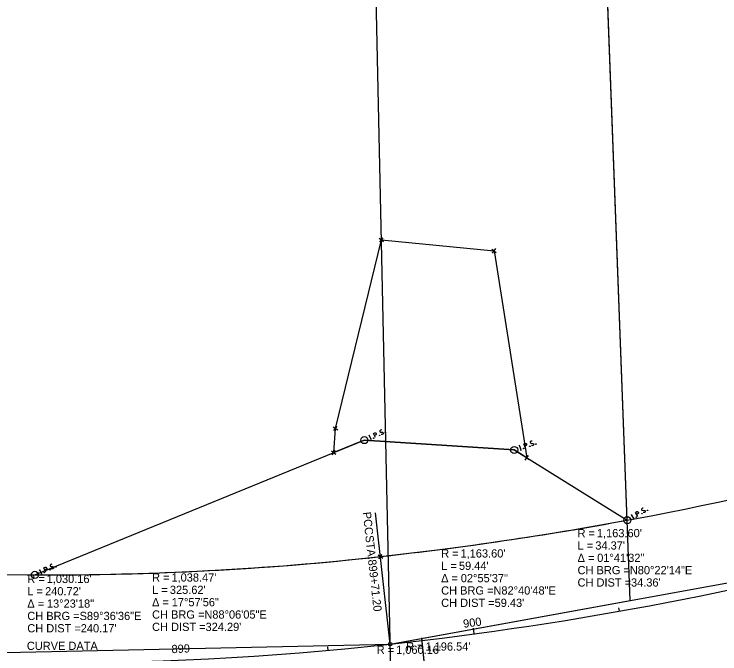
# Model space of a CAD drawing. Extents: x 2379325 to 2382869, y 256594 to 258871.
# Drawn here: x 2382072.5 to 2382312.6, y 257889.6 to 258107.4 of the extents above; entities that cross this region are included whole.
import ezdxf

# ---------------------------------------------------------------- set-up
doc = ezdxf.new("R2010")
doc.units = 0
for name, color, linetype in [('Default', 7, 'Continuous'), ('DR_P_Culvert3D', 7, 'Continuous'), ('DR_P_Dike', 7, 'Continuous'), ('DR_P_Ditch', 7, 'Continuous'), ('DR_P_Drainage_Area', 7, 'Continuous'), ('DR_P_GenericNode', 7, 'Continuous'), ('DR_P_Headwall', 7, 'Continuous'), ('DR_P_Storm_Sewer', 7, 'Continuous'), ('DR_X_Culvert', 7, 'Continuous'), ('DR_X_Culvert3D', 7, 'Continuous'), ('DR_X_Storm_Sewer', 7, 'Continuous'), ('PF_X_Ground_Line', 7, 'Continuous'), ('PTS_PVMT', 7, 'Continuous'), ('SC_Scratch2', 7, 'Continuous'), ('SC_Scratch3', 7, 'Continuous'), ('SC_Scratch4', 7, 'Continuous')]:
    doc.layers.add(name, color=color, linetype=linetype)

msp = doc.modelspace()

# ---------------------------------------------------------------- linework, layer by layer
at = {"layer": 'DR_P_Culvert3D'}
msp.add_lwpolyline([(2382181.25, 257958.12), (2382181.87, 257966.38), (2382197.46, 258030.5), (2382235.79, 258026.77), (2382246.91, 257956.37)], dxfattribs=at)
at = {"layer": 'DR_P_Dike'}
for p, q in [((2382079.62, 257916.52), (2382191.66, 257962.38)), ((2382191.66, 257962.38), (2382242.64, 257959.02)), ((2382191.66, 257962.38), (2382242.64, 257959.02)), ((2382242.64, 257959.02), (2382281.1, 257935.12))]:
    msp.add_line(p, q, dxfattribs=at)
for centre, radius, start, end in [((2382069.07, 259082.23), 1166.54, 276.30412, 280.47247), ((2382084.05, 258946.67), 1030.16, 269.75391, 276.30412)]:
    msp.add_arc(centre, radius, start, end, dxfattribs=at)
at = {"layer": 'DR_P_Ditch'}
for points in [[(2382193.16, 257963.95), (2382193.48, 257964.09)], [(2382193.99, 257962.56), (2382193.32, 257964.02)], [(2382195.41, 257963.21), (2382194.75, 257964.67), (2382195.23, 257964.89), (2382195.28, 257964.9), (2382195.36, 257964.91), (2382195.4, 257964.9), (2382195.44, 257964.89), (2382195.51, 257964.85), (2382195.57, 257964.81), (2382195.63, 257964.72), (2382195.69, 257964.59), (2382195.7, 257964.54), (2382195.71, 257964.46), (2382195.71, 257964.36), (2382195.69, 257964.31), (2382195.67, 257964.27), (2382195.63, 257964.22), (2382195.55, 257964.18), (2382195.07, 257963.96)], [(2382196.82, 257964.09), (2382196.87, 257964.11), (2382196.91, 257964.1), (2382196.96, 257964.07), (2382196.98, 257964.01), (2382196.97, 257963.95), (2382196.95, 257963.92), (2382196.9, 257963.89), (2382196.86, 257963.9), (2382196.81, 257963.94), (2382196.79, 257963.99), (2382196.8, 257964.05), (2382196.82, 257964.09)], [(2382197.53, 257965.81), (2382197.5, 257965.83), (2382197.46, 257965.84), (2382197.35, 257965.83), (2382197.23, 257965.8), (2382197.15, 257965.77), (2382197.12, 257965.75), (2382197.01, 257965.66), (2382196.93, 257965.54), (2382196.9, 257965.42), (2382196.92, 257965.31), (2382196.95, 257965.25), (2382197.02, 257965.16), (2382197.13, 257965.12), (2382197.84, 257965.03), (2382197.91, 257965), (2382197.95, 257964.97), (2382198, 257964.91), (2382198.04, 257964.84), (2382198.06, 257964.77), (2382198.07, 257964.72), (2382198.07, 257964.65), (2382198.08, 257964.59), (2382198.07, 257964.55), (2382198.06, 257964.5), (2382198.04, 257964.47), (2382198.01, 257964.42), (2382197.98, 257964.4), (2382197.9, 257964.35), (2382197.76, 257964.28), (2382197.66, 257964.26), (2382197.49, 257964.29), (2382197.38, 257964.32)], [(2382198.8, 257964.99), (2382198.85, 257965.02), (2382198.89, 257965.01), (2382198.94, 257964.98), (2382198.97, 257964.92), (2382198.96, 257964.86), (2382198.94, 257964.82), (2382198.89, 257964.8), (2382198.85, 257964.81), (2382198.8, 257964.84), (2382198.77, 257964.9), (2382198.78, 257964.96), (2382198.8, 257964.99)], [(2382193.83, 257962.49), (2382194.15, 257962.64)], [(2382194.77, 257963.16), (2382194.82, 257963.18), (2382194.86, 257963.17), (2382194.91, 257963.14), (2382194.94, 257963.08), (2382194.93, 257963.02), (2382194.91, 257962.98), (2382194.86, 257962.96), (2382194.82, 257962.97), (2382194.77, 257963), (2382194.74, 257963.06), (2382194.75, 257963.12), (2382194.77, 257963.16)], [(2382248.74, 257962.03), (2382248.71, 257962.05), (2382248.67, 257962.06), (2382248.57, 257962.06), (2382248.45, 257962.04), (2382248.36, 257962.01), (2382248.33, 257962), (2382248.21, 257961.92), (2382248.12, 257961.8), (2382248.09, 257961.68), (2382248.1, 257961.58), (2382248.13, 257961.51), (2382248.18, 257961.42), (2382248.3, 257961.37), (2382249, 257961.23), (2382249.07, 257961.2), (2382249.1, 257961.16), (2382249.15, 257961.1), (2382249.18, 257961.03), (2382249.19, 257960.95), (2382249.2, 257960.9), (2382249.2, 257960.83), (2382249.2, 257960.78), (2382249.19, 257960.74), (2382249.18, 257960.69), (2382249.15, 257960.65), (2382249.12, 257960.61), (2382249.09, 257960.59), (2382249.01, 257960.54), (2382248.86, 257960.49), (2382248.76, 257960.48), (2382248.59, 257960.51), (2382248.48, 257960.55)], [(2382244.25, 257960.48), (2382244.58, 257960.6)], [(2382244.98, 257959.04), (2382244.42, 257960.54)], [(2382244.81, 257958.98), (2382245.14, 257959.1)], [(2382245.8, 257959.58), (2382245.85, 257959.6), (2382245.89, 257959.58), (2382245.94, 257959.55), (2382245.96, 257959.49), (2382245.95, 257959.43), (2382245.93, 257959.4), (2382245.88, 257959.38), (2382245.84, 257959.39), (2382245.79, 257959.42), (2382245.77, 257959.48), (2382245.78, 257959.54), (2382245.8, 257959.58)], [(2382246.44, 257959.59), (2382245.88, 257961.09), (2382246.38, 257961.27), (2382246.44, 257961.28), (2382246.52, 257961.28), (2382246.56, 257961.27), (2382246.6, 257961.26), (2382246.66, 257961.22), (2382246.71, 257961.17), (2382246.77, 257961.08), (2382246.82, 257960.94), (2382246.83, 257960.89), (2382246.84, 257960.81), (2382246.82, 257960.71), (2382246.8, 257960.66), (2382246.77, 257960.63), (2382246.73, 257960.58), (2382246.65, 257960.54), (2382246.16, 257960.36)], [(2382247.91, 257960.36), (2382247.96, 257960.38), (2382248, 257960.37), (2382248.05, 257960.34), (2382248.07, 257960.28), (2382248.06, 257960.22), (2382248.03, 257960.18), (2382247.98, 257960.16), (2382247.94, 257960.17), (2382247.89, 257960.21), (2382247.87, 257960.27), (2382247.89, 257960.33), (2382247.91, 257960.36)], [(2382249.95, 257961.13), (2382250, 257961.15), (2382250.04, 257961.13), (2382250.09, 257961.1), (2382250.11, 257961.04), (2382250.1, 257960.98), (2382250.08, 257960.95), (2382250.03, 257960.93), (2382249.99, 257960.94), (2382249.94, 257960.97), (2382249.92, 257961.03), (2382249.93, 257961.09), (2382249.95, 257961.13)], [(2382284.74, 257936.38), (2382283.91, 257937.75), (2382284.36, 257938.03), (2382284.41, 257938.04), (2382284.49, 257938.06), (2382284.53, 257938.06), (2382284.57, 257938.05), (2382284.64, 257938.02), (2382284.71, 257937.99), (2382284.78, 257937.91), (2382284.86, 257937.78), (2382284.87, 257937.73), (2382284.89, 257937.66), (2382284.9, 257937.56), (2382284.88, 257937.5), (2382284.87, 257937.47), (2382284.83, 257937.42), (2382284.76, 257937.36), (2382284.31, 257937.09)], [(2382286.54, 257939.21), (2382286.51, 257939.22), (2382286.47, 257939.23), (2382286.36, 257939.21), (2382286.25, 257939.17), (2382286.17, 257939.12), (2382286.14, 257939.11), (2382286.04, 257939), (2382285.97, 257938.87), (2382285.96, 257938.75), (2382285.99, 257938.65), (2382286.03, 257938.58), (2382286.1, 257938.51), (2382286.22, 257938.48), (2382286.94, 257938.47), (2382287.01, 257938.46), (2382287.06, 257938.42), (2382287.12, 257938.37), (2382287.15, 257938.31), (2382287.18, 257938.24), (2382287.2, 257938.19), (2382287.21, 257938.12), (2382287.22, 257938.07), (2382287.22, 257938.02), (2382287.21, 257937.97), (2382287.2, 257937.93), (2382287.17, 257937.89), (2382287.15, 257937.86), (2382287.07, 257937.8), (2382286.94, 257937.72), (2382286.84, 257937.69), (2382286.68, 257937.69), (2382286.56, 257937.71)], [(2382286.03, 257937.42), (2382286.08, 257937.45), (2382286.12, 257937.44), (2382286.17, 257937.42), (2382286.2, 257937.36), (2382286.2, 257937.3), (2382286.19, 257937.26), (2382286.14, 257937.24), (2382286.1, 257937.24), (2382286.04, 257937.27), (2382286.01, 257937.32), (2382286.01, 257937.38), (2382286.03, 257937.42)], [(2382287.9, 257938.55), (2382287.94, 257938.58), (2382287.98, 257938.57), (2382288.04, 257938.55), (2382288.07, 257938.49), (2382288.07, 257938.43), (2382288.05, 257938.39), (2382288.01, 257938.37), (2382287.97, 257938.37), (2382287.91, 257938.4), (2382287.88, 257938.45), (2382287.88, 257938.51), (2382287.9, 257938.55)], [(2382282.42, 257936.85), (2382282.72, 257937.03)], [(2382283.4, 257935.57), (2382282.57, 257936.94)], [(2382283.25, 257935.48), (2382283.55, 257935.67)], [(2382284.11, 257936.25), (2382284.15, 257936.28), (2382284.19, 257936.28), (2382284.25, 257936.25), (2382284.28, 257936.2), (2382284.28, 257936.14), (2382284.26, 257936.1), (2382284.22, 257936.07), (2382284.18, 257936.07), (2382284.12, 257936.1), (2382284.09, 257936.15), (2382284.09, 257936.22), (2382284.11, 257936.25)], [(2382081.09, 257918.12), (2382081.41, 257918.28)], [(2382081.95, 257916.76), (2382081.25, 257918.2)], [(2382083.35, 257917.44), (2382082.66, 257918.88), (2382083.13, 257919.11), (2382083.19, 257919.12), (2382083.27, 257919.13), (2382083.31, 257919.13), (2382083.35, 257919.12), (2382083.42, 257919.08), (2382083.48, 257919.04), (2382083.54, 257918.96), (2382083.61, 257918.82), (2382083.62, 257918.77), (2382083.63, 257918.69), (2382083.63, 257918.59), (2382083.61, 257918.54), (2382083.59, 257918.5), (2382083.55, 257918.46), (2382083.47, 257918.41), (2382083, 257918.18)], [(2382084.74, 257918.35), (2382084.79, 257918.37), (2382084.83, 257918.36), (2382084.88, 257918.33), (2382084.91, 257918.28), (2382084.9, 257918.22), (2382084.88, 257918.18), (2382084.83, 257918.16), (2382084.79, 257918.16), (2382084.74, 257918.19), (2382084.71, 257918.25), (2382084.72, 257918.31), (2382084.74, 257918.35)], [(2382085.42, 257920.09), (2382085.39, 257920.1), (2382085.35, 257920.11), (2382085.24, 257920.1), (2382085.12, 257920.07), (2382085.04, 257920.03), (2382085.01, 257920.02), (2382084.9, 257919.92), (2382084.82, 257919.8), (2382084.8, 257919.68), (2382084.82, 257919.58), (2382084.85, 257919.51), (2382084.92, 257919.43), (2382085.03, 257919.39), (2382085.74, 257919.31), (2382085.82, 257919.29), (2382085.86, 257919.25), (2382085.91, 257919.19), (2382085.94, 257919.13), (2382085.97, 257919.05), (2382085.98, 257919), (2382085.99, 257918.94), (2382085.99, 257918.88), (2382085.98, 257918.84), (2382085.97, 257918.79), (2382085.95, 257918.75), (2382085.92, 257918.71), (2382085.9, 257918.69), (2382085.82, 257918.63), (2382085.68, 257918.56), (2382085.58, 257918.54), (2382085.41, 257918.56), (2382085.3, 257918.59)], [(2382086.71, 257919.3), (2382086.75, 257919.32), (2382086.8, 257919.31), (2382086.85, 257919.28), (2382086.87, 257919.23), (2382086.87, 257919.17), (2382086.85, 257919.13), (2382086.8, 257919.11), (2382086.76, 257919.11), (2382086.71, 257919.14), (2382086.68, 257919.2), (2382086.69, 257919.26), (2382086.71, 257919.3)], [(2382081.79, 257916.68), (2382082.1, 257916.84)], [(2382082.72, 257917.37), (2382082.77, 257917.39), (2382082.81, 257917.39), (2382082.86, 257917.35), (2382082.89, 257917.3), (2382082.88, 257917.24), (2382082.86, 257917.2), (2382082.81, 257917.18), (2382082.77, 257917.18), (2382082.72, 257917.22), (2382082.69, 257917.27), (2382082.7, 257917.33), (2382082.72, 257917.37)]]:
    msp.add_lwpolyline(points, dxfattribs=at)
for centre in [(2382191.66, 257962.38), (2382242.64, 257959.02), (2382281.1, 257935.12), (2382079.62, 257916.52)]:
    msp.add_circle(centre, 1.2, dxfattribs=at)
at = {"layer": 'DR_P_Drainage_Area'}
for p, q in [((2382181.87, 257966.38), (2382197.46, 258030.5)), ((2382197.46, 258030.5), (2382235.79, 258026.77)), ((2382235.79, 258026.77), (2382246.91, 257956.37)), ((2382181.25, 257958.12), (2382181.87, 257966.38)), ((2382191.66, 257962.38), (2382181.25, 257958.12)), ((2382242.64, 257959.02), (2382191.66, 257962.38)), ((2382246.91, 257956.37), (2382242.64, 257959.02))]:
    msp.add_line(p, q, dxfattribs=at)
at = {"layer": 'DR_P_GenericNode'}
msp.add_arc((2382069.07, 259082.23), 1196.54, 276.30412, 294.50972, dxfattribs=at)
at = {"layer": 'DR_P_Headwall'}
for centre, radius, start, end in [((2382069.07, 259082.23), 1166.54, 276.30412, 294.58836), ((2382069.07, 259082.23), 1226.54, 276.30412, 294.43398), ((2382084.05, 258946.67), 1030.16, 262.91573, 276.30412)]:
    msp.add_arc(centre, radius, start, end, dxfattribs=at)
at = {"layer": 'DR_P_Storm_Sewer'}
for p, q in [((2382196.7, 258031.07), (2382198.21, 258029.92)), ((2382196.89, 258029.74), (2382198.02, 258031.25)), ((2382235.02, 258027.33), (2382236.55, 258026.22)), ((2382235.24, 258026.01), (2382236.34, 258027.54)), ((2382181.11, 257966.94), (2382182.63, 257965.83)), ((2382181.32, 257965.62), (2382182.43, 257967.14)), ((2382180.5, 257958.69), (2382181.99, 257957.54)), ((2382180.67, 257957.37), (2382181.82, 257958.86)), ((2382246.13, 257956.91), (2382247.68, 257955.83)), ((2382246.37, 257955.6), (2382247.45, 257957.14)), ((2382196.42, 257923.32), (2382197.91, 257922.16)), ((2382196.59, 257922), (2382197.74, 257923.49))]:
    msp.add_line(p, q, dxfattribs=at)
at = {"layer": 'DR_X_Culvert3D'}
for p, q in [((2382278.44, 257904.15), (2382278.23, 257905.33)), ((2382229.04, 257896.43), (2382228.78, 257898.41)), ((2382179.36, 257890.81), (2382179.26, 257892))]:
    msp.add_line(p, q, dxfattribs=at)
at = {"layer": 'DR_X_Storm_Sewer'}
for p, q in [((2382282.14, 257907.78), (2382270.85, 258207.56)), ((2382200.46, 257892.92), (2382358.38, 257921.64)), ((2382240.29, 257605.16), (2382211.21, 257895.08)), ((2382240.29, 257605.16), (2382211.23, 257894.88)), ((2382069.47, 257890.07), (2382200.46, 257892.92))]:
    msp.add_line(p, q, dxfattribs=at)
at = {"layer": 'PF_X_Ground_Line'}
msp.add_line((2382227.19, 256666.69), (2382192.17, 258272.85), dxfattribs=at)
at = {"layer": 'PTS_PVMT'}
msp.add_lwpolyline([(2380915.57, 257974.64), (2381892.11, 257902.21), (2381953.3, 257894.61), (2382069.47, 257890.07), (2382200.46, 257892.92), (2382282.14, 257907.78), (2382270.85, 258207.56), (2382395.58, 258240.12), (2382408.52, 258119.54), (2382529.94, 258163.94), (2382565.45, 257993.51), (2382716.17, 258049.69), (2382661.23, 258620.32), (2382184.82, 258609.93), (2381665.09, 258580.43), (2381008.69, 258600.49), (2380481.9, 258662.85), (2379503.04, 258870.93), (2379508.92, 258601.15), (2380163.69, 258211.64)], dxfattribs=at)
at = {"layer": 'SC_Scratch2'}
for centre, radius, start, end in [((2382069.07, 259082.23), 1196.54, 276.30412, 294.50972), ((2382084.05, 258946.67), 1060.16, 262.91573, 276.30412)]:
    msp.add_arc(centre, radius, start, end, dxfattribs=at)
at = {"layer": 'SC_Scratch3'}
msp.add_line((2382200.46, 257892.92), (2382195.52, 257937.65), dxfattribs=at)
msp.add_circle((2382200.46, 257892.92), 0.6, dxfattribs=at)
at = {"layer": 'SC_Scratch4'}
for p, q in [((2382079.62, 257916.52), (2382191.66, 257962.38)), ((2382191.66, 257962.38), (2382242.64, 257959.02)), ((2382242.64, 257959.02), (2382281.1, 257935.12))]:
    msp.add_line(p, q, dxfattribs=at)

# ---------------------------------------------------------------- texts
at = {"layer": 'Default'}
for s, p in [('R = ', (2382264.19, 257929.32)), ("1,163.60'", (2382270.77, 257929.32)), ('L = ', (2382264.19, 257925.12)), ("34.37'", (2382270.23, 257925.12)), ('R = ', (2382217.8, 257922.41)), ("1,163.60'", (2382224.38, 257922.41)), ('Δ = ', (2382264.19, 257920.92)), ('01°41\'32"', (2382270.87, 257920.92)), ('L = ', (2382217.8, 257918.21)), ("59.44'", (2382223.84, 257918.21)), ('CH BRG = ', (2382264.19, 257916.72)), ('N80°22\'14"E', (2382281.97, 257916.72)), ('R = ', (2382077.03, 257913.74)), ("1,030.16'", (2382083.62, 257913.74)), ('R = ', (2382119.48, 257914.22)), ("1,038.47'", (2382126.06, 257914.22)), ('Δ = ', (2382217.8, 257914.01)), ('02°55\'37"', (2382224.48, 257914.01)), ('CH DIST = ', (2382264.19, 257912.52)), ("34.36'", (2382282.37, 257912.52)), ('L = ', (2382077.03, 257909.54)), ("240.72'", (2382083.08, 257909.54)), ('L = ', (2382119.48, 257910.02)), ("325.62'", (2382125.52, 257910.02)), ('CH BRG = ', (2382217.8, 257909.81)), ('N82°40\'48"E', (2382235.58, 257909.81)), ('Δ = ', (2382119.48, 257905.82)), ('17°57\'56"', (2382126.16, 257905.82)), ('Δ = ', (2382077.03, 257905.34)), ('13°23\'18"', (2382083.71, 257905.34)), ('CH DIST = ', (2382217.8, 257905.61)), ("59.43'", (2382235.98, 257905.61)), ('CH BRG = ', (2382077.03, 257901.14)), ('S89°36\'36"E', (2382094.81, 257901.14)), ('CH BRG = ', (2382119.48, 257901.62)), ('N88°06\'05"E', (2382137.26, 257901.62)), ('CH DIST = ', (2382077.03, 257896.94)), ("240.17'", (2382095.22, 257896.94)), ('CH DIST = ', (2382119.48, 257897.42)), ("324.29'", (2382137.66, 257897.42)), ('R = ', (2382195.88, 257889.63)), ("1,060.16'", (2382202.47, 257889.63)), ('R = ', (2382205.88, 257890.73)), ("1,196.54'", (2382212.47, 257890.73))]:
    msp.add_text(s, height=2.8, dxfattribs=at).set_placement(p)
at = {"layer": 'DR_X_Culvert'}
msp.add_text('CURVE DATA', height=2.8, dxfattribs=at).set_placement((2382076.88, 257890.96))
at = {"layer": 'DR_X_Culvert3D'}
for s, rotation, p in [('900', 7.6832, (2382225.47, 257898.47)), ('899', 2.4561, (2382126.15, 257889.85))]:
    msp.add_text(s, height=2.8, rotation=rotation, dxfattribs=at).set_placement(p)
at = {"layer": 'SC_Scratch3'}
for s, p in [('PCC', (2382191.11, 257937.8)), (' STA. ', (2382191.87, 257930.88)), ('899+71.20', (2382192.9, 257921.61))]:
    msp.add_text(s, height=2.8, rotation=276.3041, dxfattribs=at).set_placement(p)

doc.saveas('drawing.dxf')
